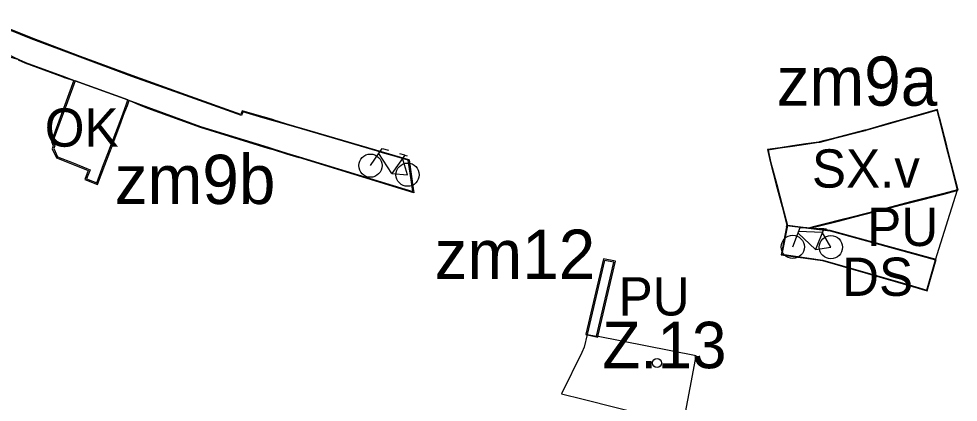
# Model space of a CAD drawing. Extents: x -555070 to -553076, y -1186731 to -1182766.
# Drawn here: x -554414.1 to -554070, y -1185354.8 to -1185214.6 of the extents above; entities that cross this region are included whole.
import ezdxf

# ---------------------------------------------------------------- set-up
doc = ezdxf.new("R2010")
doc.units = 0
for name, color, linetype in [('CYKLISTI_stav', 7, 'Continuous'), ('HRANICE_ZMENY_DO_KOO', 7, 'Continuous'), ('Level 10', 7, 'Continuous'), ('Level 13', 7, 'Continuous'), ('Level 4', 7, 'Continuous'), ('Level 46', 7, 'Continuous'), ('Level 56', 7, 'Continuous'), ('Level 59', 7, 'Continuous'), ('Level 63', 7, 'Continuous'), ('navrh_PU', 7, 'Continuous'), ('OBRYS_PLOCH', 7, 'Continuous'), ('stav_DS', 7, 'Continuous'), ('stav_OK', 7, 'Continuous'), ('stav_PU', 7, 'Continuous'), ('stav_SX', 7, 'Continuous')]:
    doc.layers.add(name, color=color, linetype=linetype)

msp = doc.modelspace()

# ---------------------------------------------------------------- linework, layer by layer
at = {"layer": 'CYKLISTI_stav'}
for p, q in [((-554285.34, -1185268.33), (-554281.06, -1185262.01)), ((-554277.47, -1185271.19), (-554282.3, -1185263.84)), ((-554281.91, -1185263.24), (-554273.58, -1185265.58)), ((-554281.06, -1185262.01), (-554278.7, -1185262.63)), ((-554272.79, -1185264.45), (-554274.55, -1185263.99)), ((-554272.79, -1185264.45), (-554277.47, -1185271.19)), ((-554271.74, -1185271.64), (-554273.58, -1185265.58)), ((-554272.79, -1185264.45), (-554271.83, -1185264.72)), ((-554277.47, -1185271.19), (-554271.74, -1185271.64)), ((-554130.66, -1185298.05), (-554127.94, -1185290.91)), ((-554127.94, -1185290.91), (-554125.5, -1185290.98)), ((-554119.32, -1185291.4), (-554122.34, -1185299.03)), ((-554119.32, -1185291.4), (-554121.14, -1185291.36)), ((-554119.32, -1185291.4), (-554118.33, -1185291.44)), ((-554122.34, -1185299.03), (-554128.73, -1185292.98)), ((-554128.48, -1185292.31), (-554119.83, -1185292.68)), ((-554116.66, -1185298.16), (-554119.83, -1185292.68)), ((-554122.34, -1185299.03), (-554116.66, -1185298.16))]:
    msp.add_line(p, q, dxfattribs=at)
for centre in [(-554285.34, -1185268.33), (-554271.74, -1185271.64), (-554130.66, -1185298.05), (-554116.67, -1185298.16)]:
    msp.add_circle(centre, 4.25, dxfattribs=at)
at = {"layer": 'HRANICE_ZMENY_DO_KOO'}
for p, q in [((-554409.52, -1185221.62), (-554427, -1185214.63)), ((-554391.6, -1185228.41), (-554409.52, -1185221.62)), ((-554372.65, -1185235.39), (-554391.6, -1185228.41)), ((-554353.01, -1185242.44), (-554372.65, -1185235.39)), ((-554332.77, -1185249.59), (-554353.01, -1185242.44)), ((-554368.85, -1185246.57), (-554366.98, -1185247.25)), ((-554366.98, -1185247.25), (-554347.69, -1185254.29)), ((-554332.31, -1185248.26), (-554332.77, -1185249.59)), ((-554324.63, -1185250.5), (-554332.31, -1185248.26)), ((-554082.82, -1185249.27), (-554090.76, -1185251.53)), ((-554077.61, -1185247.79), (-554082.82, -1185249.27)), ((-554076.89, -1185250.78), (-554077.61, -1185247.79)), ((-554320.76, -1185251.63), (-554324.63, -1185250.5)), ((-554320.76, -1185251.63), (-554316.44, -1185252.89)), ((-554316.44, -1185252.89), (-554313.1, -1185253.86)), ((-554094.86, -1185252.7), (-554103.52, -1185255.18)), ((-554090.76, -1185251.53), (-554094.86, -1185252.7)), ((-554074.23, -1185261.05), (-554076.89, -1185250.78)), ((-554347.69, -1185254.29), (-554322.92, -1185261.89)), ((-554313.1, -1185253.86), (-554310.57, -1185254.6)), ((-554310.57, -1185254.6), (-554271.35, -1185266.05)), ((-554104.23, -1185255.38), (-554115.81, -1185258.35)), ((-554103.52, -1185255.18), (-554104.23, -1185255.38)), ((-554125.85, -1185260.39), (-554130.79, -1185261.13)), ((-554121.16, -1185259.71), (-554125.85, -1185260.39)), ((-554120.84, -1185259.63), (-554121.16, -1185259.71)), ((-554115.81, -1185258.35), (-554120.84, -1185259.63)), ((-554322.92, -1185261.89), (-554321.01, -1185262.48)), ((-554321.01, -1185262.48), (-554316.05, -1185264)), ((-554316.05, -1185264), (-554311.54, -1185265.38)), ((-554135.25, -1185261.79), (-554139.91, -1185262.47)), ((-554139.91, -1185262.47), (-554138.96, -1185266.83)), ((-554130.79, -1185261.13), (-554135.25, -1185261.79)), ((-554072.57, -1185267.48), (-554074.23, -1185261.05)), ((-554269.42, -1185278.26), (-554311.54, -1185265.38)), ((-554271.35, -1185266.05), (-554271.2, -1185266.15)), ((-554271.2, -1185266.15), (-554269.66, -1185276.68)), ((-554138.96, -1185266.83), (-554136.71, -1185275.3)), ((-554070.05, -1185277.35), (-554072.57, -1185267.48)), ((-554269.66, -1185276.68), (-554269.42, -1185278.26)), ((-554075.31, -1185278.7), (-554070.05, -1185277.35)), ((-554087.42, -1185281.79), (-554075.31, -1185278.7)), ((-554134.57, -1185283.35), (-554132.79, -1185290.2)), ((-554108.42, -1185287.18), (-554096.12, -1185284.02)), ((-554096.12, -1185284.02), (-554087.42, -1185281.79)), ((-554113.45, -1185288.46), (-554108.42, -1185287.18)), ((-554124.88, -1185291.19), (-554122.35, -1185290.74)), ((-554122.35, -1185290.74), (-554113.45, -1185288.46))]:
    msp.add_line(p, q, dxfattribs=at)
for points in [[(-554397.87, -1185235.98), (-554411.82, -1185230.89), (-554414.24, -1185229.78)], [(-554397.87, -1185235.98), (-554393.48, -1185237.26), (-554374.16, -1185244.31), (-554368.85, -1185246.57)], [(-554393.93, -1185237.05), (-554396.79, -1185244.76), (-554400.79, -1185255.66)], [(-554400.79, -1185255.66), (-554402.21, -1185259.52), (-554401.52, -1185261.12), (-554401.89, -1185262.14), (-554400.29, -1185265.46), (-554394.42, -1185267.81), (-554389.4, -1185269.83), (-554388.7, -1185270.11), (-554389.94, -1185273.39), (-554385.27, -1185275.23), (-554382.59, -1185268.11), (-554380.83, -1185263.45), (-554379.98, -1185261.2), (-554379.71, -1185260.51), (-554376.6, -1185252.26), (-554375.86, -1185250.25), (-554375.5, -1185249.31), (-554374.36, -1185246.29), (-554373.71, -1185244.54)], [(-554136.71, -1185275.3), (-554134.57, -1185283.35), (-554134.57, -1185283.35)], [(-554132.9, -1185290.68), (-554134.84, -1185300.9), (-554119.71, -1185303.04), (-554086.85, -1185312.52), (-554081.37, -1185314.11), (-554078.09, -1185302.6), (-554116.93, -1185292), (-554122.28, -1185291.32)], [(-554132.9, -1185290.68), (-554132.79, -1185290.2), (-554124.88, -1185291.19), (-554122.28, -1185291.32)], [(-554201.88, -1185330.33), (-554195.55, -1185303.3), (-554199.97, -1185302.41), (-554206.41, -1185329.93), (-554206.44, -1185330.09)], [(-554206.44, -1185330.09), (-554202.01, -1185331.04), (-554201.88, -1185330.33)]]:
    msp.add_lwpolyline(points, dxfattribs=at)
at = {"layer": 'Level 13'}
for p, q in [((-554199.59, -1185303), (-554205.92, -1185330.05)), ((-554202.48, -1185330.72), (-554196.15, -1185303.69)), ((-554196.15, -1185303.69), (-554199.59, -1185303)), ((-554205.92, -1185330.05), (-554207, -1185334.66)), ((-554166.01, -1185337.84), (-554202.48, -1185330.72)), ((-554207, -1185334.66), (-554207.96, -1185336.64)), ((-554207.96, -1185336.64), (-554215.31, -1185351.82)), ((-554167.01, -1185343.09), (-554166.01, -1185337.84)), ((-554215.31, -1185351.82), (-554207.47, -1185353.77)), ((-554207.47, -1185353.77), (-554170.79, -1185362.9))]:
    msp.add_line(p, q, dxfattribs=at)
msp.add_lwpolyline([(-554170.79, -1185362.9), (-554170.35, -1185360.59), (-554167.01, -1185343.09)], dxfattribs=at)
at = {"layer": 'Level 4'}
msp.add_circle((-554180.36, -1185340.49), 1.64, dxfattribs=at)
at = {"layer": 'Level 56'}
for p, q in [((-554199.59, -1185303), (-554205.92, -1185330.05)), ((-554202.48, -1185330.72), (-554196.15, -1185303.69)), ((-554196.15, -1185303.69), (-554199.59, -1185303)), ((-554205.92, -1185330.05), (-554202.48, -1185330.72))]:
    msp.add_line(p, q, dxfattribs=at)
at = {"layer": 'navrh_PU'}
for p, q in [((-554199.59, -1185303), (-554205.92, -1185330.05)), ((-554202.48, -1185330.72), (-554196.15, -1185303.69)), ((-554196.15, -1185303.69), (-554199.59, -1185303)), ((-554205.92, -1185330.05), (-554202.48, -1185330.72))]:
    msp.add_line(p, q, dxfattribs=at)
at = {"layer": 'OBRYS_PLOCH'}
for p, q in [((-554409.63, -1185221.9), (-554427.12, -1185214.9)), ((-554409.63, -1185221.9), (-554427.12, -1185214.9)), ((-554391.7, -1185228.69), (-554409.63, -1185221.9)), ((-554391.7, -1185228.69), (-554409.63, -1185221.9)), ((-554414.14, -1185229.49), (-554414.14, -1185229.49)), ((-554414.14, -1185229.49), (-554411.71, -1185230.61)), ((-554414.14, -1185229.49), (-554414.14, -1185229.49)), ((-554414.14, -1185229.49), (-554411.71, -1185230.61)), ((-554372.75, -1185235.67), (-554391.7, -1185228.69)), ((-554372.75, -1185235.67), (-554391.7, -1185228.69)), ((-554411.71, -1185230.61), (-554398.29, -1185235.51)), ((-554411.71, -1185230.61), (-554398.29, -1185235.51)), ((-554398.29, -1185235.51), (-554393.48, -1185237.26)), ((-554398.29, -1185235.51), (-554393.48, -1185237.26)), ((-554353.11, -1185242.72), (-554372.75, -1185235.67)), ((-554353.11, -1185242.72), (-554372.75, -1185235.67)), ((-554393.48, -1185237.26), (-554396.32, -1185244.93)), ((-554374.16, -1185244.31), (-554393.48, -1185237.26)), ((-554393.48, -1185237.26), (-554374.16, -1185244.31)), ((-554393.48, -1185237.26), (-554374.16, -1185244.31)), ((-554332.59, -1185249.97), (-554353.11, -1185242.72)), ((-554332.59, -1185249.97), (-554353.11, -1185242.72)), ((-554396.32, -1185244.93), (-554400.32, -1185255.83)), ((-554375.97, -1185249.13), (-554374.83, -1185246.11)), ((-554374.83, -1185246.11), (-554374.16, -1185244.31)), ((-554374.16, -1185244.31), (-554366.88, -1185246.97)), ((-554374.16, -1185244.31), (-554366.88, -1185246.97)), ((-554377.07, -1185252.09), (-554376.33, -1185250.08)), ((-554376.33, -1185250.08), (-554375.97, -1185249.13)), ((-554366.88, -1185246.97), (-554347.59, -1185254.01)), ((-554366.88, -1185246.97), (-554347.59, -1185254.01)), ((-554332.12, -1185248.63), (-554332.59, -1185249.97)), ((-554332.12, -1185248.63), (-554332.59, -1185249.97)), ((-554324.71, -1185250.79), (-554332.12, -1185248.63)), ((-554324.71, -1185250.79), (-554332.12, -1185248.63)), ((-554380.18, -1185260.33), (-554377.07, -1185252.09)), ((-554320.84, -1185251.92), (-554324.71, -1185250.79)), ((-554320.84, -1185251.92), (-554324.71, -1185250.79)), ((-554316.52, -1185253.18), (-554320.84, -1185251.92)), ((-554316.52, -1185253.18), (-554320.84, -1185251.92)), ((-554313.18, -1185254.15), (-554316.52, -1185253.18)), ((-554313.18, -1185254.15), (-554316.52, -1185253.18)), ((-554400.32, -1185255.83), (-554401.67, -1185259.51)), ((-554347.59, -1185254.01), (-554322.83, -1185261.6)), ((-554347.59, -1185254.01), (-554322.83, -1185261.6)), ((-554310.65, -1185254.89), (-554313.18, -1185254.15)), ((-554310.65, -1185254.89), (-554313.18, -1185254.15)), ((-554271.48, -1185266.32), (-554310.65, -1185254.89)), ((-554271.48, -1185266.32), (-554310.65, -1185254.89)), ((-554401.67, -1185259.51), (-554400.98, -1185261.11)), ((-554380.45, -1185261.02), (-554380.18, -1185260.33)), ((-554400.98, -1185261.11), (-554401.35, -1185262.11)), ((-554401.35, -1185262.11), (-554399.92, -1185265.07)), ((-554383.06, -1185267.93), (-554381.3, -1185263.27)), ((-554381.3, -1185263.27), (-554380.45, -1185261.02)), ((-554322.83, -1185261.6), (-554320.92, -1185262.19)), ((-554322.83, -1185261.6), (-554320.92, -1185262.19)), ((-554320.92, -1185262.19), (-554315.96, -1185263.71)), ((-554320.92, -1185262.19), (-554315.96, -1185263.71)), ((-554315.96, -1185263.71), (-554311.45, -1185265.09)), ((-554315.96, -1185263.71), (-554311.45, -1185265.09)), ((-554399.92, -1185265.07), (-554394.23, -1185267.35)), ((-554394.23, -1185267.35), (-554389.21, -1185269.37)), ((-554311.45, -1185265.09), (-554269.79, -1185277.83)), ((-554311.45, -1185265.09), (-554269.79, -1185277.83)), ((-554270.19, -1185275.1), (-554271.48, -1185266.32)), ((-554271.48, -1185266.32), (-554271.48, -1185266.32)), ((-554271.48, -1185266.32), (-554271.48, -1185266.32)), ((-554270.19, -1185275.1), (-554271.48, -1185266.32)), ((-554271.48, -1185266.32), (-554271.48, -1185266.32)), ((-554271.48, -1185266.32), (-554271.48, -1185266.32)), ((-554388.06, -1185269.83), (-554389.3, -1185273.11)), ((-554389.21, -1185269.37), (-554388.06, -1185269.83)), ((-554385.56, -1185274.58), (-554383.06, -1185267.93)), ((-554389.3, -1185273.11), (-554385.56, -1185274.58)), ((-554269.79, -1185277.83), (-554270.55, -1185272.68)), ((-554270.55, -1185272.68), (-554270.19, -1185275.1)), ((-554269.79, -1185277.83), (-554270.55, -1185272.68)), ((-554270.55, -1185272.68), (-554270.19, -1185275.1)), ((-554134.38, -1185283.3), (-554132.61, -1185290.21)), ((-554132.61, -1185290.21), (-554134.6, -1185300.73)), ((-554199.59, -1185303), (-554205.92, -1185330.05)), ((-554202.48, -1185330.72), (-554196.15, -1185303.69)), ((-554196.15, -1185303.69), (-554199.59, -1185303)), ((-554081.51, -1185313.86), (-554078.34, -1185302.74)), ((-554205.92, -1185330.05), (-554202.48, -1185330.72))]:
    msp.add_line(p, q, dxfattribs=at)
for points in [[(-554070.29, -1185277.21), (-554072.76, -1185267.53), (-554074.42, -1185261.1), (-554077.08, -1185250.83), (-554077.76, -1185248.04), (-554082.77, -1185249.46), (-554090.71, -1185251.72), (-554094.81, -1185252.89), (-554103.47, -1185255.37)], [(-554103.47, -1185255.37), (-554104.18, -1185255.57), (-554115.76, -1185258.54), (-554120.79, -1185259.82)], [(-554120.79, -1185259.82), (-554121.12, -1185259.91), (-554125.82, -1185260.59), (-554130.76, -1185261.33), (-554135.22, -1185261.99), (-554139.67, -1185262.64), (-554138.77, -1185266.78), (-554136.52, -1185275.25), (-554134.38, -1185283.3)], [(-554070.29, -1185277.21), (-554075.36, -1185278.51), (-554087.47, -1185281.6), (-554096.17, -1185283.83), (-554108.47, -1185286.99), (-554113.5, -1185288.27), (-554118.34, -1185289.51), (-554123.18, -1185290.75), (-554124.88, -1185291.19)], [(-554096.17, -1185283.83), (-554087.47, -1185281.6), (-554075.36, -1185278.51), (-554070.29, -1185277.21)], [(-554078.34, -1185302.74), (-554073.1, -1185286.11), (-554070.29, -1185277.21)], [(-554113.5, -1185288.27), (-554108.47, -1185286.99), (-554096.17, -1185283.83)], [(-554124.88, -1185291.19), (-554127.8, -1185290.82), (-554132.61, -1185290.21)], [(-554132.61, -1185290.21), (-554127.8, -1185290.82), (-554124.88, -1185291.19)], [(-554124.88, -1185291.19), (-554123.94, -1185290.95)], [(-554124.88, -1185291.19), (-554116.97, -1185292.2), (-554078.34, -1185302.74)], [(-554078.34, -1185302.74), (-554116.97, -1185292.2), (-554124.88, -1185291.19)], [(-554122.4, -1185290.55), (-554118.34, -1185289.51), (-554113.5, -1185288.27)], [(-554134.6, -1185300.73), (-554119.67, -1185302.84), (-554086.79, -1185312.33), (-554081.51, -1185313.86)]]:
    msp.add_lwpolyline(points, dxfattribs=at)
at = {"layer": 'stav_DS'}
for p, q in [((-554409.63, -1185221.9), (-554427.12, -1185214.9)), ((-554438.02, -1185218.51), (-554414.14, -1185229.49)), ((-554391.7, -1185228.69), (-554409.63, -1185221.9)), ((-554414.14, -1185229.49), (-554411.71, -1185230.61)), ((-554372.75, -1185235.67), (-554391.7, -1185228.69)), ((-554411.71, -1185230.61), (-554398.29, -1185235.51)), ((-554398.29, -1185235.51), (-554393.48, -1185237.26)), ((-554353.11, -1185242.72), (-554372.75, -1185235.67)), ((-554393.48, -1185237.26), (-554374.16, -1185244.31)), ((-554332.59, -1185249.97), (-554353.11, -1185242.72)), ((-554374.16, -1185244.31), (-554366.88, -1185246.97)), ((-554366.88, -1185246.97), (-554347.59, -1185254.01)), ((-554332.12, -1185248.63), (-554332.59, -1185249.97)), ((-554324.71, -1185250.79), (-554332.12, -1185248.63)), ((-554320.84, -1185251.92), (-554324.71, -1185250.79)), ((-554316.52, -1185253.18), (-554320.84, -1185251.92)), ((-554313.18, -1185254.15), (-554316.52, -1185253.18)), ((-554347.59, -1185254.01), (-554322.83, -1185261.6)), ((-554310.65, -1185254.89), (-554313.18, -1185254.15)), ((-554271.48, -1185266.32), (-554310.65, -1185254.89)), ((-554322.83, -1185261.6), (-554320.92, -1185262.19)), ((-554320.92, -1185262.19), (-554315.96, -1185263.71)), ((-554315.96, -1185263.71), (-554311.45, -1185265.09)), ((-554311.45, -1185265.09), (-554269.79, -1185277.83)), ((-554271.48, -1185266.32), (-554271.48, -1185266.32)), ((-554271.48, -1185266.32), (-554271.48, -1185266.32)), ((-554270.19, -1185275.1), (-554271.48, -1185266.32)), ((-554269.79, -1185277.83), (-554270.55, -1185272.68)), ((-554270.55, -1185272.68), (-554270.19, -1185275.1)), ((-554132.61, -1185290.21), (-554134.6, -1185300.73)), ((-554116.97, -1185292.2), (-554124.88, -1185291.19)), ((-554078.34, -1185302.74), (-554116.97, -1185292.2)), ((-554081.51, -1185313.86), (-554078.34, -1185302.74))]:
    msp.add_line(p, q, dxfattribs=at)
for points in [[(-554433.27, -1185228.9), (-554430.31, -1185227.81), (-554425.9, -1185227.35), (-554422.63, -1185227.53), (-554418.91, -1185228.31), (-554416.73, -1185228.77), (-554414.14, -1185229.49)], [(-554124.88, -1185291.19), (-554127.8, -1185290.82), (-554132.61, -1185290.21)], [(-554134.6, -1185300.73), (-554119.67, -1185302.84), (-554086.79, -1185312.33), (-554081.51, -1185313.86)]]:
    msp.add_lwpolyline(points, dxfattribs=at)
at = {"layer": 'stav_OK'}
for p, q in [((-554393.48, -1185237.26), (-554396.32, -1185244.93)), ((-554374.16, -1185244.31), (-554393.48, -1185237.26)), ((-554396.32, -1185244.93), (-554400.32, -1185255.83)), ((-554375.97, -1185249.13), (-554374.83, -1185246.11)), ((-554374.83, -1185246.11), (-554374.16, -1185244.31)), ((-554377.07, -1185252.09), (-554376.33, -1185250.08)), ((-554376.33, -1185250.08), (-554375.97, -1185249.13)), ((-554380.18, -1185260.33), (-554377.07, -1185252.09)), ((-554400.32, -1185255.83), (-554401.67, -1185259.51)), ((-554401.67, -1185259.51), (-554400.98, -1185261.11)), ((-554380.45, -1185261.02), (-554380.18, -1185260.33)), ((-554400.98, -1185261.11), (-554401.35, -1185262.11)), ((-554401.35, -1185262.11), (-554399.92, -1185265.07)), ((-554383.06, -1185267.93), (-554381.3, -1185263.27)), ((-554381.3, -1185263.27), (-554380.45, -1185261.02)), ((-554399.92, -1185265.07), (-554394.23, -1185267.35)), ((-554394.23, -1185267.35), (-554389.21, -1185269.37)), ((-554388.06, -1185269.83), (-554389.3, -1185273.11)), ((-554389.21, -1185269.37), (-554388.06, -1185269.83)), ((-554385.56, -1185274.58), (-554383.06, -1185267.93)), ((-554389.3, -1185273.11), (-554385.56, -1185274.58))]:
    msp.add_line(p, q, dxfattribs=at)
at = {"layer": 'stav_PU'}
for points in [[(-554070.29, -1185277.21), (-554075.36, -1185278.51), (-554087.47, -1185281.6), (-554096.17, -1185283.83), (-554108.47, -1185286.99), (-554113.5, -1185288.27), (-554118.34, -1185289.51), (-554123.18, -1185290.75), (-554124.88, -1185291.19)], [(-554078.34, -1185302.74), (-554073.1, -1185286.11), (-554070.29, -1185277.21)], [(-554124.88, -1185291.19), (-554116.97, -1185292.2), (-554078.34, -1185302.74)]]:
    msp.add_lwpolyline(points, dxfattribs=at)
at = {"layer": 'stav_SX'}
msp.add_line((-554134.38, -1185283.3), (-554132.61, -1185290.21), dxfattribs=at)
for points in [[(-554070.29, -1185277.21), (-554072.76, -1185267.53), (-554074.42, -1185261.1), (-554077.08, -1185250.83), (-554077.76, -1185248.04), (-554082.77, -1185249.46), (-554090.71, -1185251.72), (-554094.81, -1185252.89), (-554103.47, -1185255.37)], [(-554103.47, -1185255.37), (-554104.18, -1185255.57), (-554115.76, -1185258.54), (-554120.79, -1185259.82)], [(-554120.79, -1185259.82), (-554121.12, -1185259.91), (-554125.82, -1185260.59), (-554130.76, -1185261.33), (-554135.22, -1185261.99), (-554139.67, -1185262.64), (-554138.77, -1185266.78), (-554136.52, -1185275.25), (-554134.38, -1185283.3)], [(-554096.17, -1185283.83), (-554087.47, -1185281.6), (-554075.36, -1185278.51), (-554070.29, -1185277.21)], [(-554113.5, -1185288.27), (-554108.47, -1185286.99), (-554096.17, -1185283.83)], [(-554132.61, -1185290.21), (-554127.8, -1185290.82), (-554124.88, -1185291.19)], [(-554124.88, -1185291.19), (-554123.18, -1185290.75), (-554118.34, -1185289.51), (-554113.5, -1185288.27)]]:
    msp.add_lwpolyline(points, dxfattribs=at)

# ---------------------------------------------------------------- texts
at = {"layer": 'Level 10'}
for s, p in [('zm9a', (-554136.57, -1185246.41)), ('zm9b', (-554379.01, -1185282.35)), ('zm12', (-554261.85, -1185309.73))]:
    msp.add_text(s, height=18, dxfattribs=at).set_placement(p)
at = {"layer": 'Level 46'}
msp.add_text('Z.13', height=17, dxfattribs=at).set_placement((-554200.41, -1185342.43))
at = {"layer": 'Level 59'}
for s, p in [('OK', (-554404.64, -1185261.39)), ('SX.v', (-554123.62, -1185276.37)), ('PU', (-554103.38, -1185297.72)), ('DS', (-554112.58, -1185315.96))]:
    msp.add_text(s, height=14, dxfattribs=at).set_placement(p)
at = {"layer": 'Level 63'}
msp.add_text('PU', height=14, dxfattribs=at).set_placement((-554194.43, -1185323.14))

doc.saveas('drawing.dxf')
